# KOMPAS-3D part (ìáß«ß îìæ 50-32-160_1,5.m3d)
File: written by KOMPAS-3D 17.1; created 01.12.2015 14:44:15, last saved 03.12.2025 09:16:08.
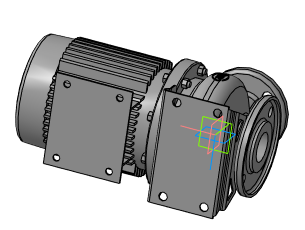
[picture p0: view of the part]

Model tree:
1. Операция без истории:6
